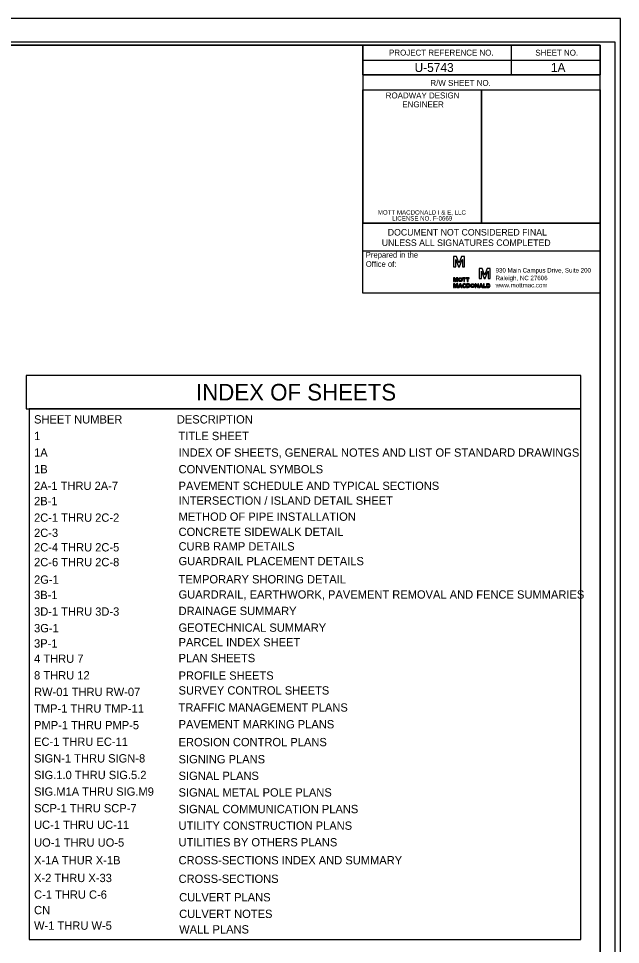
# Model space of a CAD drawing. Extents: x 5863093 to 5864777, y 1244886 to 1246112.
# Drawn here: x 5864270 to 5864777, y 1245331 to 1246112 of the extents above; entities that cross this region are included whole.
import ezdxf

# ---------------------------------------------------------------- set-up
doc = ezdxf.new("R2010")
doc.units = 0
for name, color, linetype in [('Old_Level_1', 7, 'Continuous'), ('Old_Level_2', 7, 'Continuous'), ('Old_Level_40', 7, 'Continuous'), ('Old_Level_42', 7, 'Continuous'), ('Old_Level_45', 7, 'Continuous'), ('Sheet Cutting Line CELL', 7, 'Continuous'), ('Sheet Data Field CELL', 7, 'Continuous'), ('Sheet Plan CELL', 7, 'Continuous'), ('Sheet Plot Border Inside CELL', 7, 'Continuous'), ('Sheet Plot Border Outside CELL', 7, 'Continuous'), ('Sheet Sticker Exception Certification CELL', 7, 'Continuous')]:
    doc.layers.add(name, color=color, linetype=linetype)

msp = doc.modelspace()

# ---------------------------------------------------------------- linework, layer by layer
at = {"layer": 'Old_Level_1'}
msp.add_lwpolyline([(5864278.99, 1245335.5), (5864743.56, 1245335.5), (5864743.56, 1245782.64), (5864278.99, 1245782.64)], close=True, dxfattribs=at)
at = {"layer": 'Old_Level_2'}
for p, q in [((5864638.79, 1245910.89), (5864636.27, 1245910.89)), ((5864636.27, 1245910.89), (5864636.27, 1245902.39)), ((5864638.06, 1245902.39), (5864638.06, 1245908.5)), ((5864638.06, 1245908.5), (5864638.09, 1245908.5)), ((5864638.09, 1245908.5), (5864640.48, 1245902.39)), ((5864640.84, 1245905.64), (5864638.79, 1245910.89)), ((5864642.95, 1245910.89), (5864640.9, 1245905.64)), ((5864641.26, 1245902.39), (5864643.65, 1245908.52)), ((5864645.47, 1245910.89), (5864642.95, 1245910.89)), ((5864643.65, 1245908.52), (5864643.68, 1245908.52)), ((5864643.68, 1245908.52), (5864643.68, 1245902.39)), ((5864645.47, 1245902.39), (5864645.47, 1245910.89)), ((5864636.27, 1245902.39), (5864638.06, 1245902.39)), ((5864640.48, 1245902.39), (5864641.26, 1245902.39)), ((5864640.84, 1245905.56), (5864640.84, 1245905.64)), ((5864640.9, 1245905.56), (5864640.84, 1245905.56)), ((5864640.9, 1245905.64), (5864640.9, 1245905.56)), ((5864643.68, 1245902.39), (5864645.47, 1245902.39)), ((5864660.4, 1245900.98), (5864657.88, 1245900.98)), ((5864657.88, 1245900.98), (5864657.88, 1245892.48)), ((5864662.46, 1245895.73), (5864660.4, 1245900.98)), ((5864664.56, 1245900.98), (5864662.51, 1245895.73)), ((5864667.08, 1245900.98), (5864664.56, 1245900.98)), ((5864667.08, 1245892.48), (5864667.08, 1245900.98)), ((5864637.23, 1245893.08), (5864636.27, 1245893.08)), ((5864636.27, 1245893.08), (5864636.27, 1245889.83)), ((5864638.04, 1245891.05), (5864637.23, 1245893.08)), ((5864638.84, 1245893.08), (5864638.04, 1245891.05)), ((5864639.8, 1245893.08), (5864638.84, 1245893.08)), ((5864639.8, 1245889.83), (5864639.8, 1245893.08)), ((5864639.8, 1245889.83), (5864639.8, 1245893.08)), ((5864657.88, 1245892.48), (5864659.68, 1245892.48)), ((5864659.68, 1245892.48), (5864659.68, 1245898.59)), ((5864659.68, 1245898.59), (5864659.7, 1245898.59)), ((5864659.7, 1245898.59), (5864662.09, 1245892.48)), ((5864662.09, 1245892.48), (5864662.87, 1245892.48)), ((5864662.46, 1245895.66), (5864662.46, 1245895.73)), ((5864662.51, 1245895.66), (5864662.46, 1245895.66)), ((5864662.51, 1245895.73), (5864662.51, 1245895.66)), ((5864662.87, 1245892.48), (5864665.27, 1245898.62)), ((5864665.27, 1245898.62), (5864665.29, 1245898.62)), ((5864665.29, 1245898.62), (5864665.29, 1245892.48)), ((5864665.29, 1245892.48), (5864667.08, 1245892.48)), ((5864636.27, 1245889.83), (5864636.94, 1245889.83)), ((5864637.23, 1245888.04), (5864636.27, 1245888.04)), ((5864636.27, 1245888.04), (5864636.27, 1245884.79)), ((5864636.27, 1245884.79), (5864636.94, 1245884.79)), ((5864636.94, 1245889.83), (5864636.94, 1245892.17)), ((5864636.94, 1245892.17), (5864636.97, 1245892.17)), ((5864636.94, 1245892.17), (5864636.97, 1245892.17)), ((5864636.94, 1245884.79), (5864636.94, 1245887.13)), ((5864636.94, 1245887.13), (5864636.97, 1245887.13)), ((5864636.97, 1245892.17), (5864637.88, 1245889.83)), ((5864636.97, 1245887.13), (5864637.88, 1245884.79)), ((5864638.04, 1245886.01), (5864637.23, 1245888.04)), ((5864637.88, 1245889.83), (5864638.19, 1245889.83)), ((5864637.88, 1245884.79), (5864638.19, 1245884.79)), ((5864638.84, 1245888.04), (5864638.04, 1245886.01)), ((5864638.19, 1245889.83), (5864639.1, 1245892.17)), ((5864638.19, 1245884.79), (5864639.1, 1245887.13)), ((5864639.8, 1245888.04), (5864638.84, 1245888.04)), ((5864639.1, 1245892.17), (5864639.13, 1245892.17)), ((5864639.1, 1245892.17), (5864639.13, 1245892.17)), ((5864639.1, 1245892.17), (5864639.13, 1245892.17)), ((5864639.1, 1245887.13), (5864639.13, 1245887.13)), ((5864639.13, 1245892.17), (5864639.13, 1245889.83)), ((5864639.13, 1245889.83), (5864639.8, 1245889.83)), ((5864639.13, 1245887.13), (5864639.13, 1245884.79)), ((5864639.13, 1245884.79), (5864639.8, 1245884.79)), ((5864639.8, 1245884.79), (5864639.8, 1245888.04)), ((5864646.63, 1245885.46), (5864646.07, 1245885.73)), ((5864646.63, 1245885.46), (5864646.07, 1245885.73)), ((5864646.15, 1245886.98), (5864646.71, 1245887.24)), ((5864646.15, 1245886.98), (5864646.71, 1245887.24)), ((5864648.64, 1245888.04), (5864647.16, 1245888.04)), ((5864647.16, 1245888.04), (5864647.16, 1245886.35)), ((5864647.16, 1245886.35), (5864647.16, 1245884.79)), ((5864647.16, 1245884.79), (5864648.64, 1245884.79)), ((5864647.84, 1245885.41), (5864647.84, 1245887.44)), ((5864647.84, 1245887.44), (5864648.64, 1245887.44)), ((5864648.64, 1245885.41), (5864647.84, 1245885.41)), ((5864663.98, 1245888.04), (5864663.98, 1245888.04)), ((5864665.46, 1245888.04), (5864663.98, 1245888.04)), ((5864663.98, 1245888.04), (5864663.98, 1245886.35)), ((5864663.98, 1245886.35), (5864663.98, 1245884.79)), ((5864663.98, 1245884.79), (5864665.46, 1245884.79)), ((5864664.65, 1245885.41), (5864664.65, 1245887.44)), ((5864664.65, 1245887.44), (5864665.46, 1245887.44)), ((5864665.46, 1245885.41), (5864664.65, 1245885.41)), ((5864665.46, 1245887.42), (5864665.46, 1245887.42))]:
    msp.add_line(p, q, dxfattribs=at)
for points in [[(5864643.88, 1245892.48), (5864644.82, 1245892.48), (5864644.82, 1245889.83), (5864645.52, 1245889.83), (5864645.52, 1245892.48), (5864646.46, 1245892.48), (5864646.46, 1245893.08), (5864643.88, 1245893.08), (5864643.88, 1245892.48)], [(5864646.87, 1245892.48), (5864647.81, 1245892.48), (5864647.81, 1245889.83), (5864648.51, 1245889.83), (5864648.51, 1245892.48), (5864649.45, 1245892.48), (5864649.45, 1245893.08), (5864646.87, 1245893.08), (5864646.87, 1245892.48)], [(5864640.19, 1245884.79), (5864640.97, 1245884.79), (5864641.18, 1245885.34), (5864642.59, 1245885.34), (5864642.79, 1245884.79), (5864643.55, 1245884.79), (5864642.3, 1245888.04), (5864641.44, 1245888.04), (5864640.19, 1245884.79)], [(5864641.36, 1245885.93), (5864641.88, 1245887.34), (5864642.4, 1245885.93), (5864641.36, 1245885.93)], [(5864655.11, 1245886.9), (5864655.14, 1245886.9), (5864656.7, 1245884.79), (5864657.35, 1245884.79), (5864657.35, 1245888.04), (5864656.67, 1245888.04), (5864656.67, 1245885.99), (5864655.14, 1245888.04), (5864654.46, 1245888.04), (5864654.46, 1245884.79), (5864655.11, 1245884.79), (5864655.11, 1245886.9)], [(5864657.77, 1245884.79), (5864658.54, 1245884.79), (5864658.75, 1245885.34), (5864660.16, 1245885.34), (5864660.36, 1245884.79), (5864661.12, 1245884.79), (5864659.87, 1245888.04), (5864659.01, 1245888.04), (5864657.77, 1245884.79)], [(5864658.93, 1245885.93), (5864659.46, 1245887.34), (5864659.98, 1245885.93), (5864658.93, 1245885.93)], [(5864663.59, 1245884.79), (5864663.59, 1245885.36), (5864662.18, 1245885.36), (5864662.18, 1245888.04), (5864661.51, 1245888.04), (5864661.51, 1245884.79), (5864663.59, 1245884.79)], [(5864663.59, 1245884.79), (5864663.59, 1245885.36), (5864662.18, 1245885.36), (5864662.18, 1245888.04), (5864661.51, 1245888.04), (5864661.51, 1245884.79), (5864663.59, 1245884.79), (5864663.59, 1245885.36)]]:
    msp.add_lwpolyline(points, dxfattribs=at)
msp.add_arc((5864665.46, 1245886.41), 1.62, 270, 90, dxfattribs=at)
for centre, major_axis, ratio in [((5864642.01, 1245891.46), (0, 1.62), 0.993118), ((5864642.01, 1245891.46), (0, 1.06), 0.916103), ((5864652.28, 1245886.41), (0, 1.62), 0.993118), ((5864652.28, 1245886.41), (0, 1.06), 0.916103)]:
    msp.add_ellipse(centre, major_axis=major_axis, ratio=ratio, dxfattribs=at)
for centre, major_axis, ratio, start_param, end_param in [((5864645.33, 1245886.41), (0, 1.62), 0.993118, 5.246647, 10.366427), ((5864645.33, 1245886.41), (0, 1.62), 0.993118, 5.246647, 10.366427), ((5864645.33, 1245886.41), (0, 1.06), 0.916103, 5.276876, 9.424778), ((5864645.33, 1245886.41), (0, 1.06), 0.916103, 5.276876, 10.296021), ((5864645.33, 1245886.41), (0, 1.06), 0.916103, 3.141593, 4.012835), ((5864648.64, 1245886.41), (0, -1.62), 0.930276, 0, 3.141593), ((5864648.64, 1245886.43), (0, -1.01), 0.900832, 0, 3.141593), ((5864665.46, 1245886.43), (0, -1.01), 0.900832, 0, 3.141593)]:
    msp.add_ellipse(centre, major_axis=major_axis, ratio=ratio, start_param=start_param, end_param=end_param, dxfattribs=at)
at = {"layer": 'Old_Level_40'}
msp.add_lwpolyline([(5864276.4, 1245782.64), (5864743.56, 1245782.64), (5864743.56, 1245810.64), (5864276.4, 1245810.64)], close=True, dxfattribs=at)
at = {"layer": 'Old_Level_42'}
msp.add_lwpolyline([(5864759.86, 1245880.19), (5864559.81, 1245880.19), (5864559.81, 1245915.49)], dxfattribs=at)
at = {"layer": 'Sheet Cutting Line CELL'}
msp.add_line((5864776.85, 1246111.53), (5863093.35, 1246111.53), dxfattribs=at)
at = {"layer": 'Sheet Plan CELL'}
for p, q in [((5864684.81, 1246088.98), (5864684.86, 1246063.98)), ((5864559.78, 1246076.5), (5864759.83, 1246076.49)), ((5864559.8, 1246063.96), (5864759.83, 1246063.99)), ((5864559.8, 1246063.96), (5864559.8, 1246051.48)), ((5864659.85, 1246051.48), (5864659.86, 1245939.01))]:
    msp.add_line(p, q, dxfattribs=at)
for points in [[(5863259.83, 1245039.04), (5863259.81, 1246089.01), (5864559.8, 1246089.05), (5864559.81, 1245938.99), (5864759.85, 1245938.98), (5864759.85, 1245039.04)], [(5864759.87, 1246089.04), (5863259.83, 1246089.04), (5863259.83, 1245039.04), (5864759.85, 1245039.04)], [(5864559.8, 1246089.05), (5864759.87, 1246089.04), (5864759.83, 1246063.99), (5864559.8, 1246063.96)], [(5864559.8, 1246051.48), (5864659.85, 1246051.48), (5864659.85, 1245938.96), (5864559.81, 1245938.99)], [(5864659.85, 1246051.48), (5864759.83, 1246051.49), (5864759.85, 1245938.98), (5864659.85, 1245938.96)]]:
    msp.add_lwpolyline(points, close=True, dxfattribs=at)
at = {"layer": 'Sheet Plot Border Inside CELL'}
msp.add_lwpolyline([(5863106.35, 1245036.53), (5864772.33, 1245036.54), (5864772.35, 1246091.53), (5863106.35, 1246091.53)], close=True, dxfattribs=at)
at = {"layer": 'Sheet Plot Border Outside CELL'}
msp.add_lwpolyline([(5863093.35, 1245016.53), (5864776.85, 1245016.53), (5864776.85, 1246111.53), (5863093.35, 1246111.53)], close=True, dxfattribs=at)
at = {"layer": 'Sheet Sticker Exception Certification CELL'}
for p, q in [((5864559.81, 1245915.49), (5864559.81, 1245938.99)), ((5864559.81, 1245938.99), (5864759.85, 1245938.99)), ((5864759.85, 1245938.98), (5864759.85, 1245915.48)), ((5864759.85, 1245915.49), (5864559.81, 1245915.49))]:
    msp.add_line(p, q, dxfattribs=at)

# ---------------------------------------------------------------- texts
at = {"layer": 'Old_Level_1'}
for s, p in [('SHEET NUMBER', (5864282.97, 1245770.25)), ('DESCRIPTION', (5864403.23, 1245770.25)), ('1 ', (5864282.99, 1245756.25)), ('TITLE SHEET', (5864404.66, 1245756.25)), ('1A ', (5864282.99, 1245742.25)), ('INDEX OF SHEETS, GENERAL NOTES AND LIST OF STANDARD DRAWINGS', (5864404.66, 1245742.25)), ('1B  ', (5864282.99, 1245728.25)), ('CONVENTIONAL SYMBOLS ', (5864404.69, 1245728.25)), ('2A-1 THRU 2A-7', (5864282.99, 1245714.25)), ('PAVEMENT SCHEDULE AND TYPICAL SECTIONS', (5864404.69, 1245714.25)), ('2B-1', (5864282.99, 1245701.39)), ('INTERSECTION / ISLAND DETAIL SHEET', (5864404.69, 1245701.79)), ('2C-1 THRU 2C-2  ', (5864282.99, 1245687.45)), ('METHOD OF PIPE INSTALLATION', (5864404.69, 1245688.25)), ('2C-3', (5864282.99, 1245674.66)), ('CONCRETE SIDEWALK DETAIL', (5864404.69, 1245675.46)), ('2C-4 THRU 2C-5', (5864282.99, 1245662.44)), ('CURB RAMP DETAILS', (5864404.69, 1245663.24)), ('2C-6 THRU 2C-8  ', (5864282.99, 1245649.97)), ('GUARDRAIL PLACEMENT DETAILS', (5864404.69, 1245650.77)), ('TEMPORARY SHORING DETAIL', (5864404.69, 1245635.49)), ('2G-1', (5864282.99, 1245635.22)), ('3B-1 ', (5864282.99, 1245622.29)), ('GUARDRAIL, EARTHWORK, PAVEMENT REMOVAL AND FENCE SUMMARIES', (5864404.69, 1245622.68)), ('3D-1 THRU 3D-3     ', (5864282.99, 1245608.29)), ('DRAINAGE SUMMARY', (5864404.69, 1245608.82)), ('3G-1', (5864282.99, 1245594.29)), ('GEOTECHNICAL SUMMARY', (5864404.69, 1245594.75)), ('3P-1     ', (5864282.99, 1245581.44)), ('PARCEL INDEX SHEET', (5864404.69, 1245582.44)), ('4 THRU 7    ', (5864282.99, 1245568.58)), ('PLAN SHEETS', (5864404.69, 1245569.11)), ('8 THRU 12', (5864282.99, 1245554.58)), ('PROFILE SHEETS', (5864404.69, 1245554.36)), ('SURVEY CONTROL SHEETS', (5864404.69, 1245541.83)), ('RW-01 THRU RW-07', (5864282.99, 1245540.58)), ('TMP-1 THRU TMP-11    ', (5864282.99, 1245526.58)), ('TRAFFIC MANAGEMENT PLANS', (5864404.69, 1245527.45)), ('PMP-1 THRU PMP-5   ', (5864282.99, 1245512.58)), ('PAVEMENT MARKING PLANS', (5864404.69, 1245513.34)), ('EC-1 THRU EC-11     ', (5864282.99, 1245498.58)), ('EROSION CONTROL PLANS', (5864404.69, 1245498.29)), ('SIGN-1 THRU SIGN-8     ', (5864282.99, 1245484.58)), ('SIGNING PLANS', (5864404.69, 1245483.88)), ('SIG.1.0 THRU SIG.5.2     ', (5864282.99, 1245470.58)), ('SIGNAL PLANS', (5864404.69, 1245469.88)), ('SIG.M1A THRU SIG.M9     ', (5864282.99, 1245456.58)), ('SIGNAL METAL POLE PLANS', (5864404.69, 1245455.88)), ('SCP-1 THRU SCP-7     ', (5864282.99, 1245442.58)), ('SIGNAL COMMUNICATION PLANS', (5864404.69, 1245441.88)), ('UC-1 THRU UC-11     ', (5864282.99, 1245428.58)), ('UTILITY CONSTRUCTION PLANS', (5864404.69, 1245427.88)), ('UO-1 THRU UO-5', (5864282.99, 1245413.66)), ('UTILITIES BY OTHERS PLANS', (5864404.69, 1245413.88)), ('X-1A THUR X-1B ', (5864282.99, 1245398.73)), ('CROSS-SECTIONS INDEX AND SUMMARY', (5864404.69, 1245398.73)), ('X-2 THRU X-33', (5864282.99, 1245383.81)), ('CROSS-SECTIONS', (5864404.69, 1245383.11)), ('C-1 THRU C-6', (5864282.99, 1245369.81)), ('CULVERT PLANS', (5864405.19, 1245367.55)), ('CN', (5864282.99, 1245356.73)), ('CULVERT NOTES', (5864405.19, 1245353.55)), ('W-1 THRU W-5', (5864282.99, 1245343.66)), ('WALL PLANS', (5864405.19, 1245340.47))]:
    msp.add_text(s, height=7, dxfattribs=at).set_placement(p)
at = {"layer": 'Old_Level_2'}
for s, height, p in [('Prepared in the ', 4.8186, (5864562.36, 1245909.99)), ('Office of:', 4.819, (5864562.36, 1245902.24)), ('930 Main Campus Drive, Suite 200', 3.75, (5864671.69, 1245897.47)), ('Raleigh, NC 27606', 3.75, (5864671.69, 1245891.01)), ('www.mottmac.com', 3.75, (5864671.69, 1245884.93))]:
    msp.add_text(s, height=height, rotation=360, dxfattribs=at).set_placement(p)
at = {"layer": 'Old_Level_40'}
msp.add_text('INDEX OF SHEETS', height=14, dxfattribs=at).set_placement((5864419.4, 1245789.64))
at = {"layer": 'Old_Level_45'}
for s, p in [('MOTT MACDONALD I & E, LLC', (5864572.47, 1245946.27)), (' LICENSE NO. F-0669', (5864583.1, 1245941.27))]:
    msp.add_text(s, height=3.75, rotation=360, dxfattribs=at).set_placement(p)
at = {"layer": 'Sheet Data Field CELL'}
for s, p in [('U-5743', (5864603.46, 1246066.49)), ('1A', (5864718.22, 1246066.51))]:
    msp.add_text(s, height=7.5, rotation=0, dxfattribs=at).set_placement(p)
at = {"layer": 'Sheet Plan CELL'}
for s, height, p in [('PROJECT REFERENCE NO.', 5.0001, (5864581.97, 1246080.29)), ('SHEET NO.', 5, (5864705.16, 1246080.21)), ('R/W SHEET NO.', 5.0001, (5864616.8, 1246054.78)), ('ROADWAY DESIGN', 5.0001, (5864579.17, 1246044.18)), ('ENGINEER', 5, (5864593.16, 1246036.64))]:
    msp.add_text(s, height=height, rotation=0, dxfattribs=at).set_placement(p)
at = {"layer": 'Sheet Sticker Exception Certification CELL'}
for s, p in [('DOCUMENT NOT CONSIDERED FINAL', (5864580.88, 1245928.64)), ('UNLESS ALL SIGNATURES COMPLETED', (5864575.81, 1245919.84))]:
    msp.add_text(s, height=5.5, dxfattribs=at).set_placement(p)

doc.saveas('drawing.dxf')
